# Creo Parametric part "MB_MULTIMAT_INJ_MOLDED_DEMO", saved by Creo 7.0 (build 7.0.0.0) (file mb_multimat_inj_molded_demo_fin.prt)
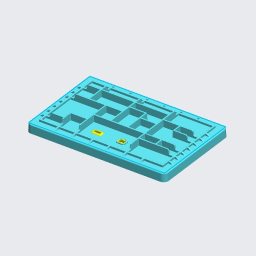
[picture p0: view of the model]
Units: millimeter Kilogram Sec (mmKs); MM, KILOGRAM, SECS
Materials in the file: PA66-GF, SILICONE_RUBBER

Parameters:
  GRANTA_DATALINK_VERSION = "5"
  GRANTA_DATABASE_KEY = "Granta_Typical_Materials"
  GRANTA_IDENTITY_GUID = "1dec458e-fa0e-4d28-aa1b-3d14c5a24b26"
  GRANTA_VERSION_GUID = "d12aeece-3595-47ca-ae7c-e67cefe245a1"
  GRANTA_MODEL_REFERENCE = "00000000-0000-0000-0000-000000000000"

Other parameters: MASS

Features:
  1. datum plane "RIGHT"
  2. datum plane "TOP"
  3. datum plane "FRONT"
  4. coordinate system
  5. curve
  6. protrusion
  7. protrusion
  8. datum plane "DTM1"
  9. datum plane "DTM2"
  10. curve
  11. protrusion
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
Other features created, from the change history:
  group "CUTOUT_PORT_W_OVERM_TYPE_A" (2 times)
  datum plane "YZ" (2 times)
  datum plane "TOP_PLUS_HEIGHT" (2 times)
  datum plane "BOTTOM_PLUS_HEIGHT" (2 times)
  sketch "Sketch 5" (2 times)
  extruded cut "Extrude 5" (2 times)
  extrusion "Extrude 6" (2 times)
  extrusion "Extrude 7" (2 times)
  round "Round 11" (2 times)
  round "Round 12" (2 times)
  protrusion "Sweep 5" (2 times)
  feature "Body Subtract 2" (2 times)
  extrusion "Extrude 8" (2 times)
  feature "Body Subtract 3" (2 times)
  planar section "XSEC0001" (3 times)
  planar section "XSEC0002"
  datum plane "DTM3"
  sketch "Sketch 6"
  feature "MASS_PROP_1" (3 times)
  feature "MASS_PROP_2" (2 times)

Other named items: HOUSING_BASE, OVERMOLD_1, CS0, HOUSING, OVERMOLD1, WITH_OVERMOLD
